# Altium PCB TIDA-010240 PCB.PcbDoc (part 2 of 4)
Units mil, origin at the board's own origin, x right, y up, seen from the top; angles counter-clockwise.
Board outline 5108.27 x 5374.02 mil, 4 copper layers (Top Layer, GND, PWR, Bottom Layer), stack 73.068 mil thick; 370 components, 162 nets, 1073 pads, 556 vias.
Unrouted connection lines stored in the file: 6.
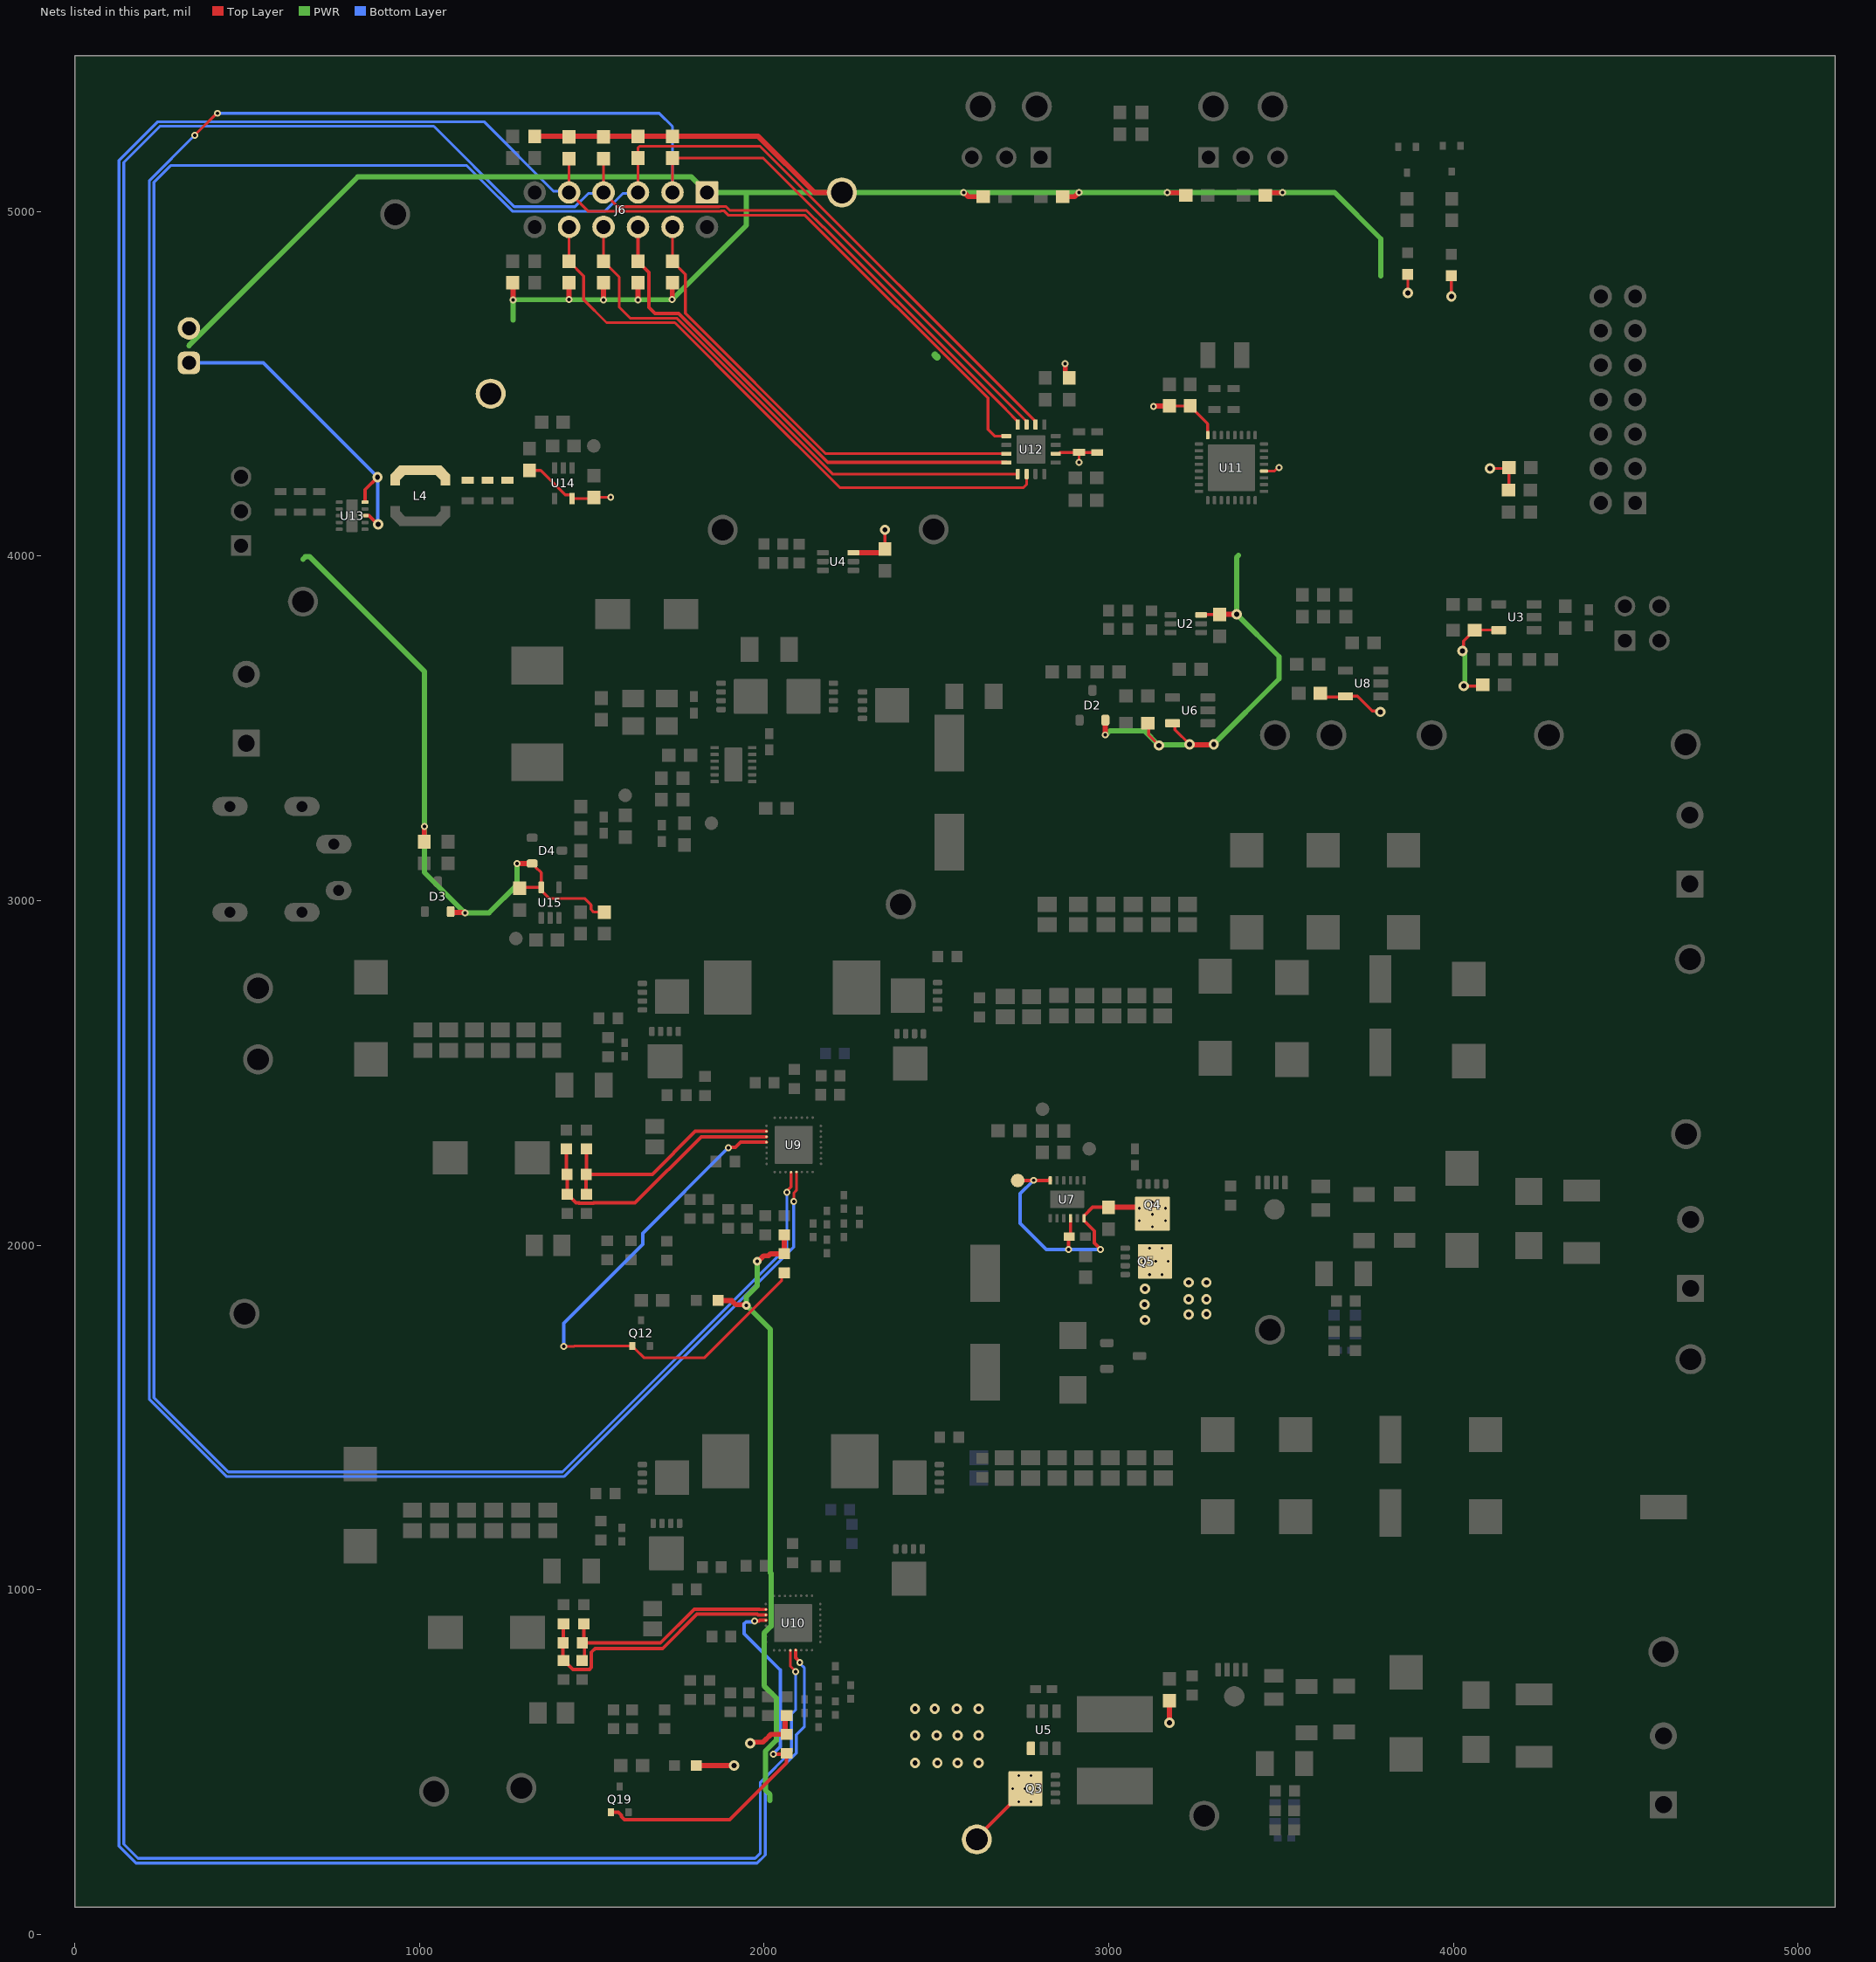
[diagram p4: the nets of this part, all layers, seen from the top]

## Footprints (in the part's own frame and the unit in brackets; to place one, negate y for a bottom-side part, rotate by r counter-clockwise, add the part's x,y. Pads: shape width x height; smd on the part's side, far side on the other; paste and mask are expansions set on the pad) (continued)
SOT-323 [mm] "Diodes Inc recommended land pattern.  2016-02-24"
  rrect21% 0.6x0.47 smd: 1(-0.95,0.65) 2(-0.95,-0.65) 3(0.95,0)
  silkscreen extent -1.14,-1.22 0.77,1.22, body extent -1.13,-1.13 1.12,1.12, height 1.13
Testpoint_Keystone_Miniature [mil] "Miniature SMT test point"
  rect 135x70 smd: 1(0,0)
  silkscreen extent -78,-46 78,45, body extent -52,-20 52,20, height 61
TI_Stacked_Overlay_Small [mil]
  silkscreen extent -418,-98 418,98
TP_SM_1MM [mm] "1mm Test Point, SMT"
  round 1 smd paste-0.5: 1(0,0)
TSW-102-07-G-S [mm] "Samtec 100mil, 1x2, 230 mil above insulator"
  rrect50% 1.65x1.65 hole 1.016: 1(-1.27,0)
  round 1.65 hole 1.016: 2(1.27,0)
  body extent -2.54,-1.27 2.54,1.27, height 8.38
TSW-106-07-G-D [mm] "Samtec 100mil, 2x6, 230 mil above insulator"
  rrect6% 1.65x1.65 hole 1.016: 1(-6.35,-1.27)
  round 1.65 hole 1.016: 2(-6.35,1.27) 3(-3.81,-1.27) 4(-3.81,1.27) 5(-1.27,-1.27) 6(-1.27,1.27) 7(1.27,-1.27) 8(1.27,1.27) 9(3.81,-1.27) 10(3.81,1.27) 11(6.35,-1.27) 12(6.35,1.27)
  silkscreen extent -8.65,-2.54 7.62,2.54, body extent -7.62,-2.54 7.62,2.54, height 8.38
WE-HCM_7070 [mm] "WURTH"
  rect 2.55x2.2 smd: 1(-2.525,0) 2(2.525,0)
  silkscreen extent -3.7,-4.1 3.7,4.1, body extent -3.75,-4.1 3.75,4.1, height 7.2
WL-SMCW_GREEN [mm] "WURTH"
  rect 0.8x0.8 smd: 1(-0.8,0) 2(0.8,0)
  silkscreen extent -1.9,-0.8 1.2,0.8, body extent -0.85,-0.45 0.85,0.45, height 0.8
XTAL_ABS07 [mm] "ABRACON"
  rect 1.1x1.9 smd: 1(-1.25,0) 2(1.25,0)
  silkscreen extent -0.4,-1 0.4,1, body extent -1.65,-0.8 1.65,0.8, height 0.9

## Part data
3.3V "3.3V Buck" BAT_A BAT_B BattORR MUX_PWR VBAT_A VBAT_B VDDA_A VDDA_B Vin VIN_FLT Vin_PROT VSYS: library part CMP-0055147-1, "Test Point, Multipurpose, Red, TH", Color=Red, Manufacturer=Keystone, Supplier Part Number 1=36-5010-ND
C1 C2 C3 C4 C5 C6 C34 C35 C36 C37 C38 C39 C42 C43 C49 C50 C51 C52 C57 C58 C66 C67 C68 C69 C88 C89 C90 C91 C92 C93 C96 C97 C103 C104 C105 C106 C111 C112 C120 C121 C122 C123: library part CMP-0008310-2, "CAP, CERM, 10 uF, 35 V, +/- 10%, X5R, 0805", Cap_Case=0805, Manufacturer=MuRata, Supplier Part Number 1=490-10514-1-ND, TempCo=X5R, Tolerance_%=10%, Value1=Unknown, Value2=35V, ValueDisplayed=10uF
C7 C29: library part CMP-0011255-3, "CAP, AL, 47 uF, 63 V, +/- 20%, SMD", Cap_Case=HA0, Manufacturer=Chemi-Con, Supplier Part Number 1=565-2151-1-ND, Tolerance_%=20%, Value1=Unknown, Value2=63V, ValueDisplayed=47uF
C8 C28: library part CMP-0007470-5, "CAP, CERM, 0.1 uF, 100 V, +/- 10%, X7R, 0603", Cap_Case=0603, Manufacturer=MuRata, Supplier Part Number 1=490-6439-1-ND, TempCo=X7R, Tolerance_%=10%, Value1=Unknown, Value2=100V, ValueDisplayed=0.1uF
C9: library part CMP-0007437-4, "CAP, CERM, 1500 pF, 50 V, +/- 10%, X7R, 0603", Cap_Case=0603, Manufacturer=MuRata, Supplier Part Number 1=490-1498-1-ND, TempCo=X7R, Tolerance_%=10%, Value1=Unknown, Value2=50V, ValueDisplayed=1500pF
C10 C11: library part CMP-0860267-1, "CAP, CERM, 22 µF, 35 V,+/- 20%, X5R, 0805", Cap_Case=0805, Manufacturer=Arrow, TempCo=X5R, Tolerance_%=20%, Value2=35V, ValueDisplayed=22µF
C12 C15 C24 C27 C31 C139 C154: library part CMP-0006356-2, "CAP, CERM, 0.1 uF, 50 V, +/- 10%, X7R, AEC-Q200 Grade 1, 0402", Cap_Case=0402, Manufacturer=MuRata, Supplier Part Number 1=490-10672-1-ND, TempCo=X7R, Tolerance_%=10%, Value1=Unknown, Value2=50V, ValueDisplayed=0.1uF
C13 C16 C18 C19 C21 C25 C30 C157: library part CMP-0086271-1, "CAP, CERM, 0.1 µF, 6.3 V,+/- 10%, X7R, 0603", Cap_Case=0603, Manufacturer=Kemet, TempCo=X7R, Tolerance_%=10%, Value2=6.3V, ValueDisplayed=0.1µF
C14 C20 C33 C53 C64 C87 C107 C118: library part CMP-0006850-4, "CAP, CERM, 0.01 uF, 50 V, +/- 5%, X7R, 0603", Cap_Case=0603, Manufacturer=Kemet, Supplier Part Number 1=399-1092-1-ND, TempCo=X7R, Tolerance_%=5%, Value1=Unknown, Value2=50V, ValueDisplayed=0.01uF
C17 C40 C41 C45 C46 C47 C81 C94 C95 C99 C100 C101 C135 C155 C156: library part CMP-0011849-2, "CAP, TA, 33 uF, 35 V, +/- 20%, 0.065 ohm, SMD", Cap_Case=7343-31, Manufacturer=Kemet, Supplier Part Number 1=399-9786-1-ND, Tolerance_%=20%, Value1="0.065 ohm", Value2=35V, ValueDisplayed=33uF
C22: library part CMP-0009478-2, "CAP, CERM, 33 uF, 35 V, +/- 20%, X7R, Stacked 2220", Cap_Case=2220, Manufacturer=MuRata, Supplier Part Number 1=490-5834-1-ND, TempCo=X7R, Tolerance_%=20%, Value1=Unknown, Value2=35V, ValueDisplayed=33uF
C23: library part CMP-0006622-2, "CAP, CERM, 0.01 uF, 6.3 V, +/- 10%, X7R, 0402", Cap_Case=0402, Manufacturer=MuRata, Supplier Part Number 1=GRM155R70J103KA01D-ND, TempCo=X7R, Tolerance_%=10%, Value1=Unknown, Value2=6.3V, ValueDisplayed=0.01uF
C26: library part CMP-0006853-4, "CAP, CERM, 0.01 uF, 16 V, +/- 10%, X7R, 0603", Cap_Case=0603, Manufacturer=Kemet, Supplier Part Number 1=399-7841-1-ND, TempCo=X7R, Tolerance_%=10%, Value1=Unknown, Value2=16V, ValueDisplayed=0.01uF
C32: library part CMP-0007304-5, "CAP, CERM, 10 uF, 6.3 V, +/- 20%, X5R, 0603", Cap_Case=0603, Manufacturer=MuRata, Supplier Part Number 1=490-7316-1-ND, TempCo=X5R, Tolerance_%=20%, Value1=Unknown, Value2=6.3V, ValueDisplayed=10uF
C44 C98: library part CMP-0007078-4, "CAP, CERM, 0.1 uF, 50 V, +/- 10%, X7R, AEC-Q200 Grade 1, 0603", Cap_Case=0603, Manufacturer=TDK, Supplier Part Number 1=445-5666-1-ND, TempCo=X7R, Tolerance_%=10%, Value1="0.0296 ohm", Value2=50V, ValueDisplayed=0.1uF
C48 C102: library part CMP-0012121-3, "CAP, Aluminum Polymer, 47 uF, 25 V, +/- 20%, 0.03 ohm, F61 SMD", Manufacturer=Panasonic, PartNumber=25SVPF47M, Tolerance_%=20%, Value1="0.03 ohm", Value2=25V, ValueDisplayed=47uF
C54 C108: library part CMP-0006254-2, "CAP, CERM, 1000 pF, 50 V, +/- 5%, C0G/NP0, 0402", Cap_Case=0402, Manufacturer=TDK, Supplier Part Number 1=445-13785-1-ND, TempCo=C0G/NP0, Tolerance_%=5%, Value1=Unknown, Value2=50V, ValueDisplayed=1000pF
C55 C61 C109 C115: library part CMP-0007449-4, "CAP, CERM, 330 pF, 50 V, +/- 10%, X7R, 0603", Cap_Case=0603, Manufacturer=MuRata, PartNumber=GRM188R71H331KA01D, Supplier Part Number 1=490-1486-1-ND, TempCo=X7R, Tolerance_%=10%, Value1=Unknown, Value2=50V, ValueDisplayed=330pF
C56 C60 C110 C114: library part CMP-0007423-4, "CAP, CERM, 0.047 uF, 25 V, +/- 10%, X7R, 0603", Cap_Case=0603, Manufacturer=MuRata, PartNumber=GRM188R71E473KA01D, Supplier Part Number 1=490-1522-1-ND, TempCo=X7R, Tolerance_%=10%, Value1=Unknown, Value2=25V, ValueDisplayed=0.047uF
C59 C79 C85 C113 C133: library part CMP-0007067-4, "CAP, CERM, 1 uF, 35 V, +/- 10%, X7R, AEC-Q200 Grade 1, 0603", Cap_Case=0603, Manufacturer=TDK, Supplier Part Number 1=445-174215-1-ND, TempCo=X7R, Tolerance_%=10%, Value1="0.005522 ohm", Value2=35V, ValueDisplayed=1uF
C62 C63 C116 C117: library part CMP-0006880-4, "CAP, CERM, 150 pF, 50 V, +/- 5%, C0G/NP0, 0603", Cap_Case=0603, Manufacturer=Kemet, PartNumber=C0603C151J5GACTU, Supplier Part Number 1=399-1063-1-ND, TempCo=C0G/NP0, Tolerance_%=5%, Value1=Unknown, Value2=50V, ValueDisplayed=150pF
C65 C119: library part CMP-0006331-2, "CAP, CERM, 0.068 uF, 50 V, +/- 10%, X7R, AEC-Q200 Grade 1, 0402", Cap_Case=0402, Manufacturer=TDK, Supplier Part Number 1=445-6898-1-ND, TempCo=X7R, Tolerance_%=10%, Value1="0.05606 ohm", Value2=50V, ValueDisplayed=0.068uF
C70 C71 C124 C125: library part CMP-0007451-4, "CAP, CERM, 0.033 uF, 50 V, +/- 10%, X7R, 0603", Cap_Case=0603, Manufacturer=MuRata, Supplier Part Number 1=490-3286-1-ND, TempCo=X7R, Tolerance_%=10%, Value1=Unknown, Value2=50V, ValueDisplayed=0.033uF
C72 C73 C126 C127: library part CMP-0007440-5, "CAP, CERM, 0.018 uF, 50 V, +/- 10%, X7R, 0603", Cap_Case=0603, Manufacturer=MuRata, Supplier Part Number 1=490-1516-1-ND, TempCo=X7R, Tolerance_%=10%, Value1=Unknown, Value2=50V, ValueDisplayed=0.018uF
C74 C128: library part CMP-0007880-2, "CAP, CERM, 0.47 uF, 50 V, +/- 10%, X7R, 0805", Cap_Case=0805, Manufacturer=TDK, Supplier Part Number 1=445-7543-1-ND, TempCo=X7R, Tolerance_%=10%, Value1="0.022012 ohm", Value2=50V, ValueDisplayed=0.47uF
C75 C129: library part CMP-0006454-2, "CAP, CERM, 33 pF, 50 V, +/- 5%, C0G/NP0, 0402", Cap_Case=0402, Manufacturer=MuRata, PartNumber=GRM1555C1H330JA01D, Supplier Part Number 1=81-GRM1555C1H330JA1D, TempCo=C0G/NP0, Tolerance_%=5%, Value1=Unknown, Value2=50V, ValueDisplayed=33pF
C76 C130: library part CMP-0007356-5, "CAP, CERM, 2.2 uF, 35 V, +/- 10%, X5R, 0603", Cap_Case=0603, Manufacturer=MuRata, PartNumber=GRM188R6YA225KA12D, Supplier Part Number 1=490-7204-6-ND, TempCo=X5R, Tolerance_%=10%, Value1=Unknown, Value2=35V, ValueDisplayed=2.2uF
C77 C131: library part CMP-0006692-2, "CAP, CERM, 4700 pF, 50 V, +/- 10%, X7R, 0402", Cap_Case=0402, Manufacturer=MuRata, Supplier Part Number 1=490-1308-1-ND, TempCo=X7R, Tolerance_%=10%, Value1=Unknown, Value2=50V, ValueDisplayed=4700pF
C78 C132: library part CMP-0006486-2, "CAP, CERM, 680 pF, 50 V, +/- 5%, C0G/NP0, 0402", Cap_Case=0402, Manufacturer=MuRata, PartNumber=GRM1555C1H681JA01D, Supplier Part Number 1=490-3240-1-ND, TempCo=C0G/NP0, Tolerance_%=5%, Value1=Unknown, Value2=50V, ValueDisplayed=680pF
C80 C134: library part CMP-0006420-2, "CAP, CERM, 15 pF, 50 V, +/- 5%, C0G/NP0, 0402", Cap_Case=0402, Manufacturer=MuRata, PartNumber=GRM1555C1H150JA01D, Supplier Part Number 1=81-GRM1555C1H150JA1D, TempCo=C0G/NP0, Tolerance_%=5%, Value1=Unknown, Value2=50V, ValueDisplayed=15pF
C82 C83 C136 C137: library part CMP-0008965-2, "CAP, CERM, 10 uF, 25 V, +/- 10%, X7R, 1206", Cap_Case=2220, Manufacturer=MuRata, PartNumber=GRM31CR71E106KA12L, Supplier Part Number 1=81-GRM31CR71E106KA12, TempCo=X7R, Tolerance_%=10%, Value1=Unknown, Value2=25V, ValueDisplayed=10uF
C84 C86 C138 C140: library part CMP-0006840-4, "CAP, CERM, 100 pF, 50 V, +/- 5%, C0G/NP0, 0603", Cap_Case=0603, Manufacturer=Kemet, PartNumber=C0603C101J5GAC, Supplier Part Number 1=1414602, TempCo=C0G/NP0, Tolerance_%=5%, Value1=Unknown, Value2=50V, ValueDisplayed=100pF
C141: library part CMP-0007160-4, "CAP, CERM, 1100 pF, 25 V, +/- 5%, C0G/NP0, 0603", Cap_Case=0603, Manufacturer=MuRata, Supplier Part Number 1=GRM1885C1E112JA01D-ND, TempCo=C0G/NP0, Tolerance_%=5%, Value1=Unknown, Value2=25V, ValueDisplayed=1100pF
C142: library part CMP-0007497-5, "CAP, CERM, 10 uF, 10 V, +/- 20%, X7R, 0603", Cap_Case=0603, Manufacturer=MuRata, Supplier Part Number 1=81-GRM188Z71A106MA3D, TempCo=X7R, Tolerance_%=20%, Value1=Unknown, Value2=10V, ValueDisplayed=10uF
C143: library part CMP-0006981-4, "CAP, CERM, 0.1 uF, 10 V, +/- 10%, X7R, 0603", Cap_Case=0603, Manufacturer=Kemet, Supplier Part Number 1=399-5343-1-ND, TempCo=X7R, Tolerance_%=10%, Value1=Unknown, Value2=10V, ValueDisplayed=0.1uF
C144: library part CMP-0006824-5, "CAP, CERM, 1 uF, 16 V, +/- 20%, X5R, 0603", Cap_Case=0603, Manufacturer="Wurth Elektronik", Supplier Part Number 1=710-885012106017, TempCo=X5R, Tolerance_%=20%, Value1=Unknown, Value2=16V, ValueDisplayed=1uF
C145: library part CMP-0007135-4, "CAP, CERM, 0.1 uF, 16 V, +/- 10%, X7R, AEC-Q200 Grade 1, 0603", Cap_Case=0603, Manufacturer=MuRata, Supplier Part Number 1=490-8015-1-ND, TempCo=X7R, Tolerance_%=10%, Value1=Unknown, Value2=16V, ValueDisplayed=0.1uF
C146 C147: library part CMP-0006765-4, "CAP, CERM, 12 pF, 50 V, +/- 5%, C0G/NP0, 0603", Cap_Case=0603, Manufacturer=AVX, Supplier Part Number 1=478-1164-1-ND, TempCo=C0G/NP0, Tolerance_%=5%, Value1="0.363 ohm", Value2=50V, ValueDisplayed=12pF
C148 C149 C151 C152: library part CMP-0007007-5, "CAP, CERM, 10 uF, 25 V, +/- 20%, X5R, 0603", Cap_Case=0603, Manufacturer=TDK, Supplier Part Number 1=445-9015-1-ND, TempCo=X5R, Tolerance_%=20%, Value1="0.004639 ohm", Value2=25V, ValueDisplayed=10uF
C150 C153: library part CMP-0006867-4, "CAP, CERM, 1 uF, 25 V, +/- 10%, X7R, 0603", Cap_Case=0603, Manufacturer=Kemet, Supplier Part Number 1=399-7376-1-ND, TempCo=X7R, Tolerance_%=10%, Value1=Unknown, Value2=25V, ValueDisplayed=1uF
D1: library part CMP-0085453-1, "Diode, TVS, Bi, 22 V, 35.5 Vc, 1500 W, 44 A, SMC (No Polarity Mark)", Manufacturer=STMicroelectronics, Value1=35.5V
D2 D3 D4: library part CMP-0076970-2, "Diode, Schottky, 40 V, 0.2 A, SOT-23", Manufacturer="Diodes Inc.", Value1=0.2A, Value2=1V
D5 D7: library part CMP-0028399-2, "Diode, Schottky, 20 V, 2 A, SMA", Manufacturer="Diodes Inc.", Value1=2A, Value2=0.5V
D6 D8 D9 D11: library part CMP-0002894-2, "LED, Green, SMD", Color=green, Manufacturer="Wurth Elektronik", Value1=W, Value2=2V
D10: library part CMP-0028387-2, "Diode, Schottky, 50 V, 1 A, SMA", Manufacturer="Diodes Inc.", Value1=1A, Value2=0.7V
GND: library part CMP-0055152-1, "Test Point, Miniature, SMT", Manufacturer=Keystone, Supplier Part Number 1=36-5015TR-ND
ILIM IN_ISNS SYS_IAVG SYS_IFLT SYS_ISNS: library part CMP-0055149-1, "Test Point, Multipurpose, White, TH", Color=White, Manufacturer=Keystone, Supplier Part Number 1=36-5012-ND
J1 J2 J3 J10: library part CMP-0074910-1, "Terminal Block, 5.08 mm, 2x1, Brass, TH", Color=Blue, Current_A=15A, Manufacturer="On-Shore Technology", PartNumber=ED120/2DS, Supplier Part Number 1=ED1609-ND, Voltage_V=300V
J4: library part CMP-0054695-2, "Header (shrouded), 100 mil, 7x2, Gold, TH", Manufacturer="Sullins Connector Solutions", Supplier Part Number 1=S9170-ND
J5 J7 J8: library part CMP-0002338-1, "Header, 100mil, 3x1, Tin, TH", Color=Black, Current_A=3A, Manufacturer="Sullins Connector Solutions", Supplier Part Number 1=S1012E-03-ND, Voltage_V=1.8kV
J6: library part CMP-0075412-1, "Header, 100mil, 6x2, Gold, TH", Color=Black, Current_A=6.3A, Manufacturer=Samtec, Supplier Part Number 1=SAM1028-06-ND, Voltage_V=550V
J9: library part CMP-0075405-2, "Header, 100mil, 2x1, Gold, TH", Color=Black, Current_A=6.3A, Manufacturer=Samtec, Supplier Part Number 1=SAM1029-02-ND, Voltage_V=550V
J11: library part CMP-0087344-2, Current_A=6.3A, Manufacturer=Samtec, Voltage_V=550V
J12: library part CMP-0092549-1, Current_A=6.5A, Digikey Part Number=102-5565-1-ND, Manufacturer="CUI Devices", Mouser Part Number=490-PJ-098H, Operating Temperature Range="-25°C to +85°C", Voltage_V=24V
L1: library part CMP-0063904-1, "Inductor, Shielded Drum Core, Ferrite, 160 nH, 29 A, 0.00033 ohm, SMD", Manufacturer="Wurth Elektronik", Supplier Part Number 1=732-3009-1-ND, Value1="0.00033 ohm", Value2=29A, ValueDisplayed=160nH
L2 L3: library part CMP-0088941-1, "2.2µH Shielded Wirewound Inductor 13A 9mOhm Max 10x10x3mm", Manufacturer="Chilisin Electronics", Operating Temperature Range="-55°C to +125°C", Test Frequency=100kHz, Tolerance_%=20%
L4: library part CMP-0060461-1, "Inductor, Shielded Drum Core, Ferrite, 10 uH, 0.75 A, 0.35 ohm, SMD", Manufacturer=Coilcraft, Value1="0.35 ohm", Value2=0.75A, ValueDisplayed=10uH
Logo1: library part CMP-0074838-1, "Texas Instrument Corporate Signature"
Logo2: library part CMP-0074847-1, "FCC_disclaimer"
LOGO3: library part CMP-0074844-1
Q1 Q3 Q4: library part CMP-0079500-2, "MOSFET, N-CH, 30 V, 60 A, DNH0008A (VSONP-8)", Alternate Manufacturer=None, Manufacturer="Texas Instruments", Supplier Part Number 1=CSD17581Q3A-ND, Value1="0.0047 ohm", Value2="20 nC"
Q2 Q5 Q6 Q7 Q8 Q9 Q11 Q13 Q14 Q15 Q16: library part CMP-0000591-2, "MOSFET, N-CH, 30 V, 14 A, DNH0008A (VSONP-8)", Alternate Manufacturer=None, Manufacturer="Texas Instruments", Supplier Part Number 1=CSD17578Q3A-ND, Value1=0.008, Value2="7.9 nC"
Q10 Q17: library part CMP-0092727-1, "P-Channel 30 V 5.1 mOhm 57 W TrenchFET Gen III Mosfet - PowerPAK 1212-8S", Digikey Part Number=SISS27ADN-T1-GE3CT-ND, Drain To Source Breakdown Voltage=-30V, Input Capacitace At Vds="4660pF @ -15V", Manufacturer=Vishay, Mouser Part Number=78-SISS27ADN-T1-GE3, Operating Temperature Range="-55°C to +150°C", Power_W=4.8W, Pulse Drain Current=-200A, Typ Forward Diode Voltage=-0.8V
Q12 Q18 Q19 Q20: library part CMP-0000643-2, "MOSFET, N-CH, 30 V, 0.18 A, SOT-323", Alternate Manufacturer=None, Manufacturer=Nexperia, Supplier Part Number 1=568-10508-1-ND, Value1=5, Value2="0.34 nC"
Q21: library part CMP-0000420-2, "Transistor, NPN, 45 V, 0.5 A, SOT-23", Manufacturer="ON Semiconductor", Supplier Part Number 1=BC817-16LT1GOSCT-ND, Value1="0.5 A", Value2=250
R1 R2: library part CMP-0081623-1, "RES, 0.002, 1%, 1 W, AEC-Q200 Grade 0, 1206", Manufacturer=Rohm, Power_W=1W, Supplier Part Number 1=RHM.002ALCT-ND, TempCo="100 ppm/C", Tolerance_%=1%, Value_Code=2L000, ValueDisplayed=0.002
R3 R4 R10 R11 R26 R30 R50 R54: library part CMP-0022478-4, "RES, 4.99, 1%, 0.1 W, AEC-Q200 Grade 0, 0603", Manufacturer=Vishay-Dale, PartNumber=CRCW06034R99FKEA, Power_W=100mW, Supplier Part Number 1=541-4.99HHCT-ND, TempCo="100 ppm/C", Tolerance_%=1%, Value2=0.1W, Value_Code=4R99, ValueDisplayed=4.99
R5 R12 R13 R14 R16 R19 R40 R64 R96 R97: library part CMP-0022735-5, "RES, 100 k, 1%, 0.1 W, 0603", Manufacturer=Yageo, Power_W=100mW, Supplier Part Number 1=311-100KHRCT-ND, TempCo="100 ppm/C", Tolerance_%=1%, Value2=0.1W, Value_Code=100k
R6: library part CMP-0023872-3, "RES, 1.15 k, 0.1%, 0.1 W, 0603", Manufacturer="Yageo America", Power_W=100mW, TempCo="25 ppm/C", Tolerance_%=0.1%, Value2=0.1W, Value_Code=1k15, ValueDisplayed=1.15k
R7: library part CMP-0022969-4, "RES, 280 k, 1%, 0.1 W, 0603", Manufacturer=Yageo, Power_W=100mW, Supplier Part Number 1=311-280KHRCT-ND, TempCo="100 ppm/C", Tolerance_%=1%, Value2=0.1W, Value_Code=280k, ValueDisplayed=200k
R8: library part CMP-0022553-1, "RES, 68.1, 1%, 0.1 W, 0603", Manufacturer=Vishay-Dale, Power_W=100mW, Supplier Part Number 1=541-68.1HCT-ND, TempCo="100 ppm/C", Tolerance_%=1%, Value2=0.1W, Value_Code=68R1, ValueDisplayed=68.1
R9: library part CMP-0022735-5, "RES, 100 k, 1%, 0.1 W, 0603", Manufacturer=Yageo, Power_W=100mW, Supplier Part Number 1=311-100KHRCT-ND, TempCo="100 ppm/C", Tolerance_%=1%, Value2=0.1W, Value_Code=100k, ValueDisplayed=75k
R15: library part CMP-0022924-5, "RES, 22.6 k, 1%, 0.1 W, 0603", Manufacturer=Yageo, Power_W=100mW, Supplier Part Number 1=311-22.6KHRCT-ND, TempCo="100 ppm/C", Tolerance_%=1%, Value2=0.1W, Value_Code=22k6, ValueDisplayed=22.6k
R17: library part CMP-0022996-5, "RES, 2.70 k, 1%, 0.1 W, 0603", Manufacturer=Yageo, Power_W=100mW, Supplier Part Number 1=311-2.70KHRCT-ND, TempCo="100 ppm/C", Tolerance_%=1%, Value2=0.1W, Value_Code=2k70, ValueDisplayed=2.70k
R20 R87: library part CMP-0025446-1, "RES, 5.97 k, 0.5%, 0.1 W, 0603", Manufacturer="Yageo America", Power_W=100mW, TempCo="50 ppm/C", Tolerance_%=0.5%, Value2=0.1W, Value_Code=5k97, ValueDisplayed=5.97k
R21 R88: library part CMP-0023258-5, "RES, 715, 1%, 0.1 W, 0603", Manufacturer=Yageo, Power_W=100mW, Supplier Part Number 1=311-715HRCT-ND, TempCo="100 ppm/C", Tolerance_%=1%, Value2=0.1W, Value_Code=715R, ValueDisplayed=715
R22 R41: library part CMP-0023870-1, "RES, 1.13 k, 0.1%, 0.1 W, 0603", Manufacturer="Yageo America", Power_W=100mW, TempCo="25 ppm/C", Tolerance_%=0.1%, Value2=0.1W, Value_Code=1k13, ValueDisplayed=1.13k
R23 R24 R47 R48: library part CMP-0084411-1, "RES, 0.005, 1%, 1 W, AEC-Q200 Grade 0, 1206", Manufacturer=Vishay-Dale, Power_W=1W, TempCo="110 ppm/C", Tolerance_%=1%, Value_Code=5L000, ValueDisplayed=0.005
R25 R49: library part CMP-0020833-2, "RES, 0, 1%, 0.5 W, 0805", Manufacturer=Keystone, Power_W=500mW, Supplier Part Number 1=36-5106CT-ND, TempCo=ppm/C, Tolerance_%=1%, Value2=0.5W, Value_Code=0
R27 R31 R51 R55: library part CMP-0025829-4, "RES, 56, 5%, 0.1 W, AEC-Q200 Grade 0, 0603", Manufacturer=Vishay-Dale, PartNumber=CRCW060356R0JNEA, Power_W=100mW, Supplier Part Number 1=541-56GCT-ND, TempCo="200 ppm/C", Tolerance_%=5%, Value2=0.1W, Value_Code=56R0, ValueDisplayed=56
R28 R29 R52 R53: library part CMP-0025703-4, "RES, 10, 5%, 0.1 W, AEC-Q200 Grade 0, 0603", Manufacturer=Vishay-Dale, PartNumber=CRCW060310R0JNEA, Power_W=100mW, Supplier Part Number 1=541-10GCT-ND, TempCo="200 ppm/C", Tolerance_%=5%, Value2=0.1W, Value_Code=10R0, ValueDisplayed=10
R32 R56: library part CMP-0020487-3, "RES, 1.0, 5%, 0.125 W, AEC-Q200 Grade 0, 0805", Manufacturer=Vishay-Dale, PartNumber=CRCW08051R00JNEA, Power_W=125mW, Supplier Part Number 1=541-1.0ACT-ND, TempCo="200 ppm/C", Tolerance_%=5%, Value2=0.125W, Value_Code=1R00, ValueDisplayed=1.0
R33 R57: library part CMP-0026027-3, "RES, 15.0 k, 1%, 0.063 W, AEC-Q200 Grade 0, 0402", Manufacturer=Vishay-Dale, Power_W=63mW, Supplier Part Number 1=541-15.0KLCT-ND, TempCo="100 ppm/C", Tolerance_%=1%, Value2=0.063W, Value_Code=15k0, ValueDisplayed=15.0k
R34 R58: library part CMP-0026367-2, "RES, 40.2 k, 1%, 0.063 W, AEC-Q200 Grade 0, 0402", Manufacturer=Vishay-Dale, PartNumber=CRCW040240K2FKED, Power_W=63mW, Supplier Part Number 1=541-40.2KLCT-ND, TempCo="100 ppm/C", Tolerance_%=1%, Value2=0.063W, Value_Code=40k2, ValueDisplayed=40.2k
R35 R59: library part CMP-0025703-4, "RES, 10, 5%, 0.1 W, AEC-Q200 Grade 0, 0603", Manufacturer=Vishay-Dale, Power_W=100mW, Supplier Part Number 1=541-10GCT-ND, TempCo="200 ppm/C", Tolerance_%=5%, Value2=0.1W, Value_Code=10R0, ValueDisplayed=10
R36 R60: library part CMP-0016044-3, "RES, 0, 5%, 0.75 W, AEC-Q200 Grade 0, 2010", Manufacturer=Vishay-Dale, Power_W=750mW, Supplier Part Number 1=541-0.0WCT-ND, TempCo=ppm/C, Tolerance_%=5%, Value2=0.75W, Value_Code=0000, ValueDisplayed=0
R37 R61: library part CMP-0025786-4, "RES, 33 k, 5%, 0.1 W, AEC-Q200 Grade 0, 0603", Manufacturer=Vishay-Dale, Power_W=100mW, Supplier Part Number 1=541-33KGCT-ND, TempCo="200 ppm/C", Tolerance_%=5%, Value2=0.1W, Value_Code=33k0, ValueDisplayed=33k
R38 R39 R62 R63: library part CMP-0021998-4, "RES, 10.0 k, 1%, 0.1 W, AEC-Q200 Grade 0, 0603", Manufacturer=Vishay-Dale, PartNumber=CRCW060310K0FKEA, Power_W=100mW, Supplier Part Number 1=541-10.0KHCT-ND, TempCo="100 ppm/C", Tolerance_%=1%, Value2=0.1W, Value_Code=10k0, ValueDisplayed=10.0k
R42 R66: library part CMP-0022101-4, "RES, 191 k, 1%, 0.1 W, AEC-Q200 Grade 0, 0603", Manufacturer=Vishay-Dale, Power_W=100mW, Supplier Part Number 1=541-191KHCT-ND, TempCo="100 ppm/C", Tolerance_%=1%, Value2=0.1W, Value_Code=191k
R43 R67: library part CMP-0021990-4, "RES, 100 k, 1%, 0.1 W, AEC-Q200 Grade 0, 0603", Manufacturer=Vishay-Dale, Power_W=100mW, Supplier Part Number 1=541-100KHCT-ND, TempCo="100 ppm/C", Tolerance_%=1%, Value2=0.1W, Value_Code=100k
R44 R68: library part CMP-0022324-4, "RES, 30.1 k, 1%, 0.1 W, AEC-Q200 Grade 0, 0603", Manufacturer=Vishay-Dale, PartNumber=CRCW060330K1FKEA, Power_W=100mW, Supplier Part Number 1=541-30.1KHCT-ND, TempCo="100 ppm/C", Tolerance_%=1%, Value2=0.1W, Value_Code=30k1, ValueDisplayed=30.1k
R45 R65 R73 R74 R75 R76 R77 R78 R79 R80 R81 R82 R83: library part CMP-0023148-5, "RES, 4.30 k, 1%, 0.1 W, 0603", Manufacturer=Yageo, Power_W=100mW, Supplier Part Number 1=311-4.30KHRCT-ND, TempCo="100 ppm/C", Tolerance_%=1%, Value2=0.1W, Value_Code=4k30, ValueDisplayed=4.30k
R46 R70 R86 R90: library part CMP-0022918-5, "RES, 220, 1%, 0.1 W, 0603", Manufacturer=Yageo, Power_W=100mW, Supplier Part Number 1=311-220HRCT-ND, TempCo="100 ppm/C", Tolerance_%=1%, Value2=0.1W, Value_Code=220R, ValueDisplayed=220
R69 R71 R93 R94 R103 R104 R105 R106 R107 R108 R109: library part CMP-0023343-3, "RES, 0, 1%, 0.1 W, AEC-Q200 Grade 0, 0603", Manufacturer="Stackpole Electronics Inc", Power_W=100mW, Supplier Part Number 1=RMCF0603ZT0R00CT-ND, TempCo=ppm/C, Tolerance_%=1%, Value2=0.1W, Value_Code=0
R72: library part CMP-0023133-5, "RES, 47.0 k, 1%, 0.1 W, 0603", Manufacturer=Yageo, Power_W=100mW, Supplier Part Number 1=311-47.0KHRCT-ND, TempCo="100 ppm/C", Tolerance_%=1%, Value2=0.1W, Value_Code=47k0, ValueDisplayed=47.0k
R84: library part CMP-0025394-1, "RES, 53.0 k, 0.5%, 0.1 W, 0603", Manufacturer="Yageo America", Power_W=100mW, TempCo="50 ppm/C", Tolerance_%=0.5%, Value2=0.1W, Value_Code=53k0, ValueDisplayed=50.0k
R85 R99: library part CMP-0022090-2, "RES, 17.8 k, 1%, 0.1 W, 0603", Manufacturer=Vishay-Dale, Power_W=100mW, Supplier Part Number 1=541-17.8KHCT-ND, TempCo="100 ppm/C", Tolerance_%=1%, Value2=0.1W, Value_Code=17k8, ValueDisplayed=17.8k
R89 R100: library part CMP-0023291-5, "RES, 82.5 k, 1%, 0.1 W, 0603", Manufacturer=Yageo, Power_W=100mW, Supplier Part Number 1=311-82.5KHRCT-ND, TempCo="100 ppm/C", Tolerance_%=1%, Value2=0.1W, Value_Code=82k5, ValueDisplayed=82.5k
R91 R92: library part CMP-0024334-3, "RES, 54.9 k, 0.1%, 0.1 W, 0603", Manufacturer="Yageo America", Power_W=100mW, TempCo="25 ppm/C", Tolerance_%=0.1%, Value2=0.1W, Value_Code=54k9, ValueDisplayed=54.9k
R95 R101: library part CMP-0022391-4, "RES, 3.57 M, 1%, 0.1 W, AEC-Q200 Grade 0, 0603", Manufacturer=Vishay-Dale, Power_W=100mW, Supplier Part Number 1=541-3.57MHCT-ND, TempCo="100 ppm/C", Tolerance_%=1%, Value2=0.1W, Value_Code=3M57, ValueDisplayed=3.57M
TP1 TP2 TP3 TP4: library part CMP-0055149-2, "Test Point, Multipurpose, White, TH", Color=White, Manufacturer="Keystone Electronics", PartNumber=5012, Supplier Part Number 1=36-5012-ND
TP5 TP6 TP7 TP8 TP9 TP10 TP11: library part CMP-0003825-1, "1mm Test Point, SMT", Manufacturer=Any
TP12 TP13 TP14 TP15 TP17: library part CMP-0055148-2, "Test Point, Multipurpose, Black, TH", Color=Black, Manufacturer="Keystone Electronics", Supplier Part Number 1=36-5011-ND
U1 U7: library part CMP-0089212-1, "Ideal Diode Controller with Load Dump Protection", Manufacturer="Texas Instruments", Max Supply Voltage=65V, Min Supply Voltage=3V, Nominal Supply Current=428uA, Operating Temperature Range="-40°C to +150°C"
U2 U4: library part CMP-0077336-3, "26-V, Bi-Directional, Zero-Drift, High Accuracy, Low-/High-Side, Voltage Out Current Shunt Monitor, DCK0006A (SOT-SC70-6)", Alternate Manufacturer="Texas Instruments", Alternate PartNumber=INA213BIDCKT, Operating Temperature Range="-40 to 125 C", Rating=Catalog
U3 U6 U8: library part CMP-0090312-1, "General Purpose Amplifier 1 Circuit Rail-to-Rail SOT-23-5", Digikey Part Number=296-TLV9051IDBVRCT-ND, Input Bias Current=0.000002uA, Input Offset Voltage=0.33mV, Manufacturer="Texas Instruments", Max Supply Voltage=5.5V, Min Supply Voltage=1.8V, Mouser Part Number=595-TLV9051IDBVR, Nominal Supply Current=330uA, Operating Temperature Range="-40°C to +125°C", Output Current Per Channel=50mA, Voltage Gain=104dB
U5: library part CMP-0013281-4, "Low Iq Always ON Smart Diode Controller, DBV0006A (SOT-23-6)", Alternate Manufacturer="Texas Instruments", Alternate PartNumber=LM74700QDBVTQ1
U9 U10: library part CMP-0089013-3, "No Description", Manufacturer="Texas Instruments", Operating Temperature Range=to
U11: library part CMP-0081775-2, "Mixed-Signal Microcontroller, RHB0032E (VQFN-32)", Alternate Manufacturer="Texas Instruments", Alternate PartNumber=MSP430FR2475TRHBT, Operating Temperature Range="-40 to 105 C", Rating=Catalog
U12: library part CMP-0043160-2, "4-Channel I2C and SMBus Multiplexer with Reset Functions, 2.3 to 5.5 V, -40 to 85 degC, 16-pin VQFN (RGV), Green (RoHS & no Sb/Br)", 5V Tolerant I/O=Yes, Manufacturer="Texas Instruments", Max Frequency(kHz)=400
U13: library part CMP-0067107-3, "28V, 0.5A Step-Down Converter with SNOOZE Mode, DQC0010A (WSON-10)", Alternate Manufacturer="Texas Instruments", Alternate PartNumber=TPS62177DQCT
U14 U15: library part CMP-0860137-1, "Small-Size Nanopower Low-Voltage Comparator, DCK0005A (SOT-SC70-5)", Alternate Manufacturer="Texas Instruments", Alternate PartNumber=TLV7031DCKT, Operating Temperature Range="-40 to 125 C", Rating=Catalog
Y1: library part CMP-0004628-3, "CRYSTAL, 32.768KHz, 12.5PF, SMD", Frequency Stability=+/-20ppm, Frequency_Fixed=32.768kHz, Manufacturer="Abracon Corporation", Supplier Part Number 1=535-9542-1-ND
ZZ1: library part CMP-0003616-3
ZZ2: library part CMP-0077236-1
ZZ3: library part CMP-0077237-1
ZZ4: library part CMP-0077238-1

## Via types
v1: diameter 30, hole 15, Top Layer to Bottom Layer, tented both sides, 281 vias
v2: diameter 19.68, hole 7.87, Top Layer to Bottom Layer, 102 vias
v3: diameter 20, hole 10, Top Layer to Bottom Layer, tented both sides, 99 vias
v4: diameter 24, hole 12, Top Layer to Bottom Layer, tented both sides, 19 vias
v5: diameter 23.62, hole 11.81, Top Layer to Bottom Layer, 18 vias
v6: diameter 19.68, hole 7.87, Top Layer to Bottom Layer, tented both sides, 14 vias
v7: diameter 28, hole 14, Top Layer to Bottom Layer, tented both sides, 13 vias
v8: diameter 25, hole 10, Top Layer to Bottom Layer, tented both sides, 8 vias
v9: diameter 18, hole 8, Top Layer to Bottom Layer, tented both sides, 2 vias

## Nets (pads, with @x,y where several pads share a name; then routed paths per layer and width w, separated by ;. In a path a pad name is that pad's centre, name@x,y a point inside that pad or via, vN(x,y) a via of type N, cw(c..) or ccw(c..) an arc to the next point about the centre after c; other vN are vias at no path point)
3.3V: 3.3V.1 C13.1 C16.1 C19.1 C21.1 C25.1 C30.1 C142.1 C143.1 C144.1 C145.1 C157.1 D2.2 D3.2 D4.2 D6.2 D8.2 D9.2 D11.2 J6.1 J9.2 R5.2 R7.1 R16.2 R22.2 R38.2 R39.2 R41.2 R45.2 R62.2 R63.2 R65.2 R71.1 R72.2 R73.2 R74.2 R75.2 R76.2 R77.2 R78.2 R79.2 R80.2 R81.2 R82.2 R83.2 R97.2 U2.3 U3.5 U4.3 U6.5 U8.5 U11.20 U11.32 U12.14 U14.5 U15.5 | length 13368.1
  Top Layer w8: C157.1@1290.46,3035.81 1293.41,3038.77 U15.5@1353.45,3038.77 ; R16.2@1318.9,4249.03 1351.84,4249.03 1422.77,4178.1 1439.04,4178.1 1442.91,4174.22 U14.5@1442.91,4167.33 1502.95,4167.33 C16.1@1505.91,4170.29 1506.25,4170.63 v3(1554.88,4170.63) ; D4.2@1326.77,3108.11 1329.68,3108.11 1337.35,3100.44 1337.35,3097.54 1353.45,3081.43 U15.5@1353.45,3038.77 ; R97.2@1536.52,2966.92 1505.82,2966.92 1497.94,2974.8 1497.94,2987.72 1478.78,3006.88 1376.49,3006.88 1353.45,3029.91 U15.5@1353.45,3038.77 ; C21.1@2350.64,4020.27 v1(2350.64,4076.52) ; U12.14@2846.35,4297.35 2855.21,4297.35 2858.77,4300.92 C145.1@2913.82,4300.92 ; C145.1@2913.44,4301.52 2913.82,4301.14 C145.1@2913.82,4300.92 ; v3(2913.82,4272.35) C145.1@2913.82,4300.92 ; C144.1@2966.27,4300.92 C145.1@2913.82,4300.92 ; C25.1@3113.27,3515.1 3115.77,3512.59 3115.77,3480.63 v1(3145.8,3450.6) ; C142.1@3175.78,4435.87 C143.1@3236.3,4435.87 3236.3,4434.88 3287.13,4384.05 U11.32@3287.13,4351.31 ; U6.5@3185.12,3515.1 3190.32,3515.1 3192.13,3513.29 3192.13,3496.4 v1(3234.33,3454.2) ; U2.3@3266.93,3830.46 U2.3@3267.99,3829.4 3276.85,3829.4 3278.35,3830.89 C13.1@3321.93,3830.89 ; U11.20@3450.52,4246.98 3481,4246.98 3490.85,4256.82 v3(3494.09,4256.82) ; C30.1@3602.01,3595.94 C30.1@3603.91,3597.84 ; C30.1@3613.75,3591.19 3684.75,3591.19 U8.5@3686.65,3593.09 ; U8.5@3686.7,3595.22 3687.98,3593.94 3721.62,3593.94 3764.69,3550.87 3785.53,3550.87 v1(3788.4,3548) ; v1(3867.55,4764.02) D11.2@3867.55,4817.6 ; v1@3994.07,4754.31 D9.2@3994.07,4813.37 ; v1(4026.47,3724.92) 4029.34,3727.79 4029.34,3753.87 4060.85,3785.38 C19.1@4061.84,3785.38 U3.5@4131.72,3785.38 ; v1(4030.34,3623.1) 4081.68,3623.1 R7.1@4085.04,3626.45 ; v1(4106.19,4254.17) 4158.77,4254.17 R71.1@4161.42,4256.82 4161.42,4192.69 R72.2@4160.59,4191.86
  Top Layer w15: R5.2@1013.78,3171.26 1013.88,3171.36 1013.88,3215.29 v3(1013.98,3215.39) ; D3.2@1090.55,2968.5 1093.39,2965.66 1130.93,2965.66 v3(1131.89,2964.71) ; R41.2@1270.67,4793.31 1271.24,4792.73 1271.24,4744.67 v3(1271.82,4744.09) ; v3(1283.44,3108.11) D4.2@1326.77,3108.11 ; R22.2@1334.11,5218.5 R76.2@1634.11,5218.5 R75.2@1734.11,5218.5 1982.99,5218.5 2145.85,5055.64 3.3V.1@2225.55,5055.64 ; v3(1434.11,4744.67) R81.2@1434.11,4793.31 ; v3(1534.11,4744.07) R82.2@1534.11,4793.31 ; v3(1633.88,4744.07) R79.2@1633.88,4793.31 ; v3(1733.09,4744.67) 1733.6,4745.18 1733.6,4791.77 R80.2@1733.09,4792.28 ; D8.2@1803.26,490.1 v1(1912.75,490.1) ; D6.2@1866.5,1840.2 1867.48,1839.22 1906.08,1839.22 1917.75,1827.55 1946.67,1827.55 v8(1948.58,1825.64) ; v1(1959.42,555.03) 1962.29,557.9 1996.32,557.9 2004.61,566.19 2005.39,566.19 2019.84,580.63 R63.2@2065.26,580.63 2061.21,584.69 2061.21,630.72 R62.2@2065.26,634.78 ; v8(1980.28,1953.81) 1982.98,1953.81 1998.49,1969.32 2012.62,1969.32 2018.75,1975.45 R39.2@2058.33,1975.45 R38.2@2058.33,2030.55 ; U4.3@2259.11,4009.92 C21.1@2338.32,4009.92 ; v3(2578.74,5055.64) 2580.09,5055.64 2592.28,5043.46 R65.2@2635.83,5043.46 ; R45.2@2866.04,5043.46 2901.2,5043.46 v3(2913.39,5055.64) ; v3(2872.87,4558.8) 2872.87,4557.44 2873.92,4556.4 2873.92,4528.76 R83.2@2885.12,4517.56 ; v3(2990.03,3481.14) 2990.1,3481.2 2990.1,3524.08 D2.2@2990.16,3524.14 ; v3(3129.92,4434.88) 3130.41,4435.38 3175.29,4435.38 C142.1@3175.78,4435.87 ; v3(3169.29,5055.64) 3170.25,5054.69 3216.11,5054.69 R73.2@3223.5,5047.29 ; v1@3234.33,3452.4 3302.82,3452.4 v1(3304.62,3454.2) ; C13.1@3321.93,3830.89 3322.31,3831.27 3370.47,3831.27 v1(3370.85,3831.64) ; R74.2@3454.39,5047.29 3461.78,5054.69 3502.98,5054.69 v3(3503.94,5055.64)
  Top Layer w20: R80.2@1733.09,4792.28 R80.2@1734.11,4793.31 ; D9.2@3993.93,4813.51 D9.2@3994.07,4813.37 ; v1@3994.07,4754.31 v1(3994.21,4754.17)
  PWR w15: 331.13,4611.16 820.6,5100.62 1789.13,5100.62 J6.1@1834.11,5055.64 1948.82,5055.64 ; 661.86,3991.07 668.99,3998.19 681.42,3998.19 1013.98,3665.63 v3(1013.98,3215.39) 1013.98,3082.62 v3(1131.89,2964.71) 1201.56,2964.71 1283.44,3046.58 v3(1283.44,3108.11) ; 1271.82,4685.04 v3(1271.82,4744.09) 1272.1,4744.38 1732.8,4744.38 v3(1733.09,4744.67) 1948.82,4960.4 1948.82,5055.64 ; v8(1980.28,1953.81) 1980.28,1882.53 1948.58,1850.83 v8(1948.58,1825.64) 2018.13,1756.09 2018.13,1049.43 2020.24,1047.33 2020.24,894.74 1999.74,874.24 1999.74,721.66 2035.66,685.73 2035.66,563.83 2003.92,532.08 2003.92,418.84 2017.16,405.6 2017.16,388.67 ; v3(2990.03,3481.14) 2991.39,3481.14 3003.72,3493.48 3102.92,3493.48 v1(3145.8,3450.6) 3147.6,3452.4 3302.82,3452.4 v1(3304.62,3454.2) 3494.09,3643.67 3494.09,3708.4 v1(3370.85,3831.64) 3370.85,3996.57 3376.68,4002.4 ; 3789.37,4812.99 3789.37,4921.26 3654.99,5055.64 v3(3503.94,5055.64) v3(3169.29,5055.64) v3(2913.39,5055.64) v3(2578.74,5055.64) 3.3V.1@2225.55,5055.64 1948.82,5055.64 ; v1(4026.47,3724.92) 4026.47,3720.86 4033.38,3713.95 4033.38,3645.06 4033.21,3644.9 4033.21,3625.97 v1(4030.34,3623.1)
  PWR w20: 2495.36,4584.12 2501.9,4577.58
3.3V_Buck: "3.3V Buck.1" C151.1 C152.1 C153.1 J9.1 L4.2 U13.8 U13.10 | length 958.8
  Top Layer w10: U13.8@841.92,4117.36 853.12,4117.36 878.32,4092.17 v1(879.88,4092.17) ; U13.10@841.92,4156.73 841.92,4193.12 v1(878.32,4229.52)
  Bottom Layer w10: J9.1@331.13,4561.16 546.68,4561.16 v1(878.32,4229.52) 879.1,4228.74 879.1,4092.95 v1(879.88,4092.17)
ACN_A: C64.2 C71.1 R30.1 U9.2 | length 707.2
  Top Layer w10: C71.1@1484.38,2147.68 1483.53,2148.54 C64.2@1483.53,2205.9 ; R30.1@1484.38,2279.28 1484.38,2206.76 C64.2@1483.53,2205.9 ; U9.2@2006.74,2330.76 1800.45,2330.76 1675.58,2205.9 C64.2@1483.53,2205.9
ACN_B: C118.2 C125.1 R54.1 U10.2 | length 678.8
  Top Layer w10: R54.1@1477.13,901.41 1477.13,851.13 C118.2@1471.98,845.98 ; C125.1@1478.88,801.7 1478.88,839.08 C118.2@1471.98,845.98 ; U10.2@2004.94,943.03 1987.68,943.03 1986.53,944.18 1797.46,944.18 1699.26,845.98 C118.2@1471.98,845.98
ACP_A: C64.1 C70.1 R26.1 U9.3 | length 801.4
  Top Layer w10: R26.1@1426.44,2279.28 1426.44,2207.87 C64.1@1428.41,2205.9 C70.1@1428.41,2147.68 1429.39,2147.68 1454.14,2122.93 1462.51,2122.93 1463.51,2121.93 1505.26,2121.93 1506.26,2122.93 1625.33,2122.93 1817.41,2315.01 U9.3@2006.74,2315.01
ACP_B: C118.1 C124.1 R50.1 U10.3 | length 797.7
  Top Layer w10: R50.1@1418.07,901.41 1416.86,900.2 C118.1@1416.86,845.98 1416.56,845.68 1416.56,797.3 1444.8,769.05 1492.86,769.05 1498.71,774.91 1498.71,818.87 1509.82,829.97 1705.68,829.97 1804.89,929.18 1980.32,929.18 1982.22,927.28 U10.3@2004.94,927.28
BAT_A_SCL: J6.6 R79.1 U12.8 | length 1470.3
  Top Layer w10: J6.6@1634.11,4955.64 1634.11,4856.53 R79.1@1633.88,4856.3 1633.88,4855.31 1665.33,4823.87 1665.33,4722.47 1683.07,4704.72 1751.85,4704.72 1762.18,4694.4 2184.81,4271.76 U12.8@2702.65,4271.76
BAT_A_SDA: J6.4 R80.1 U12.7 | length 1366.2
  Top Layer w8: J6.4@1734.11,4955.64 R80.1@1734.11,4856.3 1734.11,4855.31 1771.65,4817.78 1771.65,4704.72 2179.02,4297.35 U12.7@2702.65,4297.35
BAT_B_SCL: J6.10 R81.1 U12.10 | length 1774.2
  Top Layer w8: J6.10@1434.11,4955.64 R81.1@1434.11,4856.3 1434.11,4855.31 1476.38,4813.05 1476.38,4744.09 1542.75,4677.72 1740.67,4677.72 1972.92,4445.48 2219.64,4198.75 2752.08,4198.75 2761.71,4208.38 U12.10@2761.71,4238.3
BAT_B_SDA: J6.8 R82.1 U12.9 | length 1609.1
  Top Layer w8: J6.8@1534.11,4955.64 R82.1@1534.11,4856.3 1534.11,4855.31 1579.64,4809.79 1579.64,4722.47 1611.38,4690.72 1746.06,4690.72 1940.93,4495.85 2198.48,4238.3 U12.9@2736.11,4238.3
BattORR: BattORR.1 C28.1 C31.1 C85.2 Q3.5 Q3.6 Q3.7 Q3.8 Q3.9 Q4.5 Q4.6 Q4.7 Q4.8 Q4.9 Q5.5 Q5.6 Q5.7 Q5.8 Q5.9 TP9.1 U5.4 U7.6 U7.10 U7.12 | length 1148.8
  Top Layer w10: BattORR.1@2617.03,275.57 2617.03,280.61 2756.48,420.07 v2(2756.48,422.92) ; TP9.1@2735.79,2187.94 2736.08,2188.24 2781.82,2188.24 v3(2782.12,2188.53) 2782.29,2188.36 2829.09,2188.36 U7.6@2829.09,2189.11 ; U7.6@2829.09,2193.18 U7.6@2829.09,2189.11 ; U7.6@2830.01,2188.18 U7.6@2829.09,2189.11 ; v3(2883.86,1988.19) C31.1@2883.86,2027.56 ; C31.1@2889.07,2031.98 U7.10@2889.07,2078.74 ; v3(2975.59,1988.19) 2975.59,1989.15 2958.4,2006.35 2958.4,2041.65 2928.44,2071.61 U7.12@2928.44,2078.74 2928.44,2085.86 2952.81,2110.23 C28.1@2999.26,2110.23 ; Q4.9@3085.54,2110.23 v2(3088.34,2107.43)
  Top Layer w15: C28.1@2999.26,2110.23 Q4.9@3085.54,2110.23 ; C85.2@3176.07,678.74 3176.22,678.59 3176.22,614.38 v1(3176.36,614.24)
  Bottom Layer w10: v3(2782.12,2188.53) 2743.01,2149.43 2743.01,2063.85 2818.68,1988.19 v3(2883.86,1988.19) v3(2975.59,1988.19)
  other v1: 2437.93,497.97 2502.77,497.97 2561.71,497.97 2622,497.97 2437.93,577.29 2500.56,577.29 2561.71,577.29 2622,577.29 2437.93,654.68 2495.07,654.68 2558.87,654.68 2622,654.68 3105.37,1783.06 3231.9,1798.76 3283.29,1800.25 3103.78,1827.84 3231.9,1843.42 3283.29,1843.42 3105.49,1873.42 3231.9,1892.16 3283.29,1892.16
  other v2: 2738.67,384.53 2774.3,384.53 2792.11,422.92 2738.67,461.31 2774.3,461.31 3118.45,1914.9 3154.08,1914.9 3100.64,1953.28 3136.27,1953.28 3118.45,1991.67 3154.08,1991.67 3088.34,2071.8 3165.11,2071.8 3126.72,2089.62 3165.11,2107.43 3126.72,2125.25
  other v6: 2720.85,422.92 3171.9,1953.28 3126.72,2053.99
CHG_A_SCL: J6.3 R75.1 U9.13 U12.3 | length 9255.6
  Top Layer w8: v3(347.61,5221.46) 411.58,5285.43 v3(413.39,5285.43) ; J6.3@1734.11,5055.64 R75.1@1734.11,5155.51 1997.05,5155.51 2761.71,4390.86 U12.3@2761.71,4382 ; v3(2085.9,2127.01) 2086.41,2127.52 2086.41,2152.01 2093.76,2159.36 U9.13@2093.76,2212.65
  Bottom Layer w8: v3(347.61,5221.46) 216.54,5090.38 216.54,1552.29 439.81,1329.02 1420.14,1329.02 2085.9,1994.78 v3(2085.9,2127.01) ; v3(413.39,5285.43) 1695.73,5285.43 1734.11,5247.05 J6.3@1734.11,5055.64
CHG_A_SDA: J6.5 R76.1 U9.12 U12.2 | length 9073.3
  Top Layer w8: J6.5@1634.11,5055.64 R76.1@1634.11,5155.51 1634.11,5185.13 1638.8,5189.82 1988.34,5189.82 2787.3,4390.86 U12.2@2787.3,4382 ; v3(2065.9,2153.86) 2065.9,2157.11 2078.01,2169.22 U9.12@2078.01,2212.24
  Bottom Layer w8: J6.5@1634.11,5055.64 1630.97,5052.5 1589.63,5052.5 1538.3,5001.16 1269.82,5001.16 1189.39,5081.6 1137.44,5133.55 278.09,5133.55 229.54,5085 229.54,1557.67 445.19,1342.02 1414.76,1342.02 2065.9,1993.16 v3(2065.9,2153.86)
CHG_B_SCL: J6.9 R77.1 U10.13 U12.5 | length 10602
  Top Layer w8: R77.1@1434.11,5153.64 J6.9@1434.11,5055.64 1488.6,5001.16 1874.57,5001.16 1875.32,5001.92 1884.38,5001.92 1897.05,4989.24 2118.54,4989.24 2383.37,4724.41 2384.73,4724.41 2649.57,4459.58 2649.57,4367.54 2668.57,4348.54 U12.5@2702.65,4348.54
  Top Layer w10: U10.13@2091.96,824.92 2091.96,802.5 2103.56,790.91 v3(2103.56,789.17)
  Bottom Layer w8: J6.9@1434.11,5055.64 1430.97,5058.79 1389.63,5058.79 1187.36,5261.06 240.48,5261.06 127.95,5148.54 127.95,256.17 177.43,206.69 1979.74,206.69 2003.21,230.17 2003.21,435.72 2093.43,525.93 2093.43,579.82 2117.07,603.46 2117.07,772.96 2103.56,786.47 v3(2103.56,789.17)
CHG_B_SDA: J6.7 R78.1 U10.12 U12.4 | length 10523.7
  Top Layer w8: R78.1@1534.11,5153.64 J6.7@1534.11,5055.64 1575.6,5014.16 1869.18,5014.16 1869.94,5014.92 1889.76,5014.92 1901.54,5003.14 2123.02,5003.14 2170.52,4955.64 2171.89,4955.64 2701.46,4426.06 2701.46,4425.51 2736.11,4390.86 U12.4@2736.11,4382 ; U10.12@2076.22,824.51 2076.22,778.37 2091.52,763.07 v3(2091.52,762.57)
  Bottom Layer w8: J6.7@1534.11,5055.64 1530.97,5052.5 1489.63,5052.5 1451.3,5014.16 1275.21,5014.16 1041.34,5248.03 247.24,5248.03 141.95,5142.74 141.95,261.96 183.22,220.69 1973.94,220.69 1989.21,235.97 1989.21,441.51 2079.43,531.73 2079.43,639.48 2091.52,651.57 v3(2091.52,762.57)
CHG_OK_A: Q12.1 R39.1 U9.4 | length 1675.2
  Top Layer w8: v3(1418.74,1706.75) 1448.54,1706.75 1449.52,1707.73 Q12.1@1617.48,1707.73 1617.48,1705.17 1622.73,1699.92 1625.29,1699.92 1652.1,1673.11 1826.46,1673.11 2050.62,1897.27 2050.62,1912.62 R39.1@2070.08,1932.08
  Top Layer w10: v3(1895.93,2282.68) 1897.84,2284.6 1917.09,2284.6 1931.75,2299.27 U9.4@2006.74,2299.27
  Bottom Layer w10: v3(1418.74,1706.75) 1418.74,1773.79 1647.74,2002.79 1647.74,2034.65 1895.78,2282.68 v3(1895.93,2282.68)
CHG_OK_B: Q19.1 R63.1 U10.4 | length 1155
  Top Layer w10: Q19.1@1555.36,354.6 1559.14,354.6 1559.61,354.13 1576.61,354.13 1585.45,345.29 1585.45,341.62 1594.28,332.79 1900.29,332.79 2065.26,497.77 R63.1@2065.26,525.51 2062.51,522.76 v3(2026.42,522.76) ; v3(1972.03,909.18) 1984.91,909.18 1987.27,911.53 U10.4@2004.94,911.53
  Bottom Layer w10: v3(1972.03,909.18) 1970.12,907.27 1963.05,907.27 1947.6,907.26 1941.74,901.41 1941.74,872.59 2046.56,767.77 2046.56,545.05 2026.42,524.9 v3(2026.42,522.76)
